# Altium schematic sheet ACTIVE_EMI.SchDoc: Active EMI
size A4; DrawnBy: Hely Zhang; Organization: Altium Limited; Address1: L3, 12a Rodborough Rd; Address2: Frenchs Forest; Address3: NSW; Address4: Australia 2086; DocumentNumber: 6; SheetNumber: 6; SheetTotal: 6; PageSetup: Record=PageOptions¦CenterHorizontal=True¦CenterVertical=True¦PrintScale=0.93¦XCorrection=1.00¦YCorrection=1.00¦PrintKind=0¦BorderSize=5000000¦LeftOffset=0¦BottomOffset=0¦Orientation=2¦PaperLength=1000¦PaperWidth=1000¦Scale=100¦PaperSource=15¦PrintQuality=600¦MediaType=1¦DitherType=10¦PaperKind=Letter¦PrintScaleMode=1
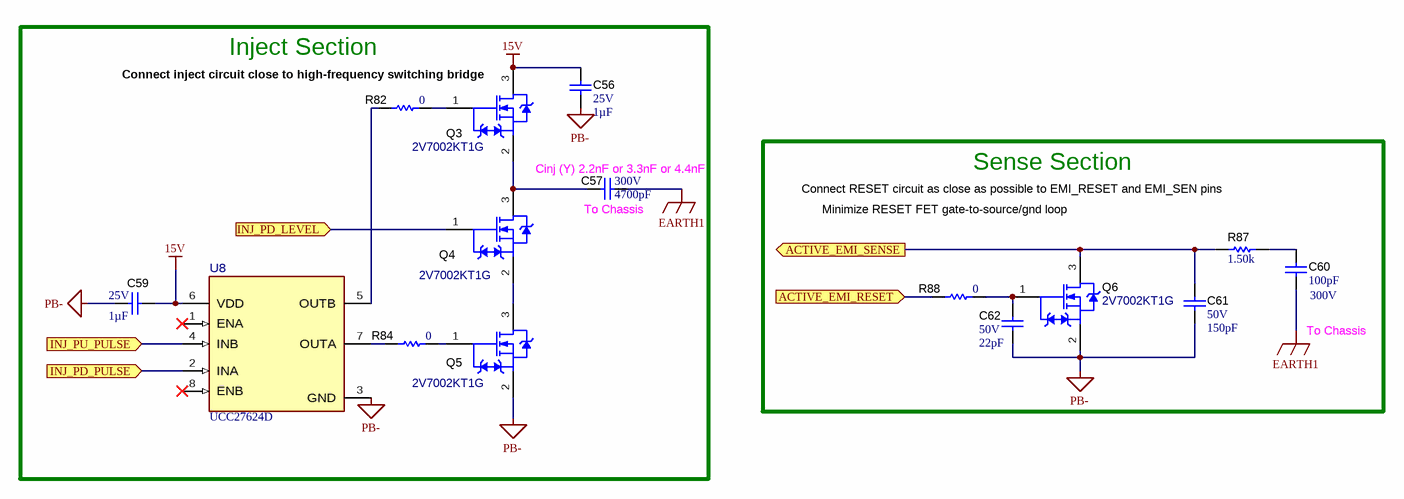
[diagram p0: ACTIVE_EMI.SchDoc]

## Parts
C56  VDC_V: 25V  Cap_F: 1µF  [0603]  (hidden comment: GRJ188R71E105KE11D)
C57  VDC_V: 300V  ValueDisplayed: 4700pF  [AY2_1300x500_Straight]  (hidden comment: AY2472M49Y5US63L7)
C59  VDC_V: 25V  Cap_F: 1µF  [0603]  (hidden comment: GRJ188R71E105KE11D)
C60  ValueDisplayed: 100pF  VAC_Y: 300V  [KY_700x500x1000]  (hidden comment: DE2B3KY101KN3AU02F)
C61  VDC_V: 50V  ValueDisplayed: 150pF  [0603]  (hidden comment: GRM1885C1H151JA01D)
C62  VDC_V: 50V  ValueDisplayed: 22pF  [0603]  (hidden comment: GRM1885C1H220JA01D)
Q3  2V7002KT1G  [SOT-23]
Q4  2V7002KT1G  [SOT-23]
Q5  2V7002KT1G  [SOT-23]
Q6  2V7002KT1G  [SOT-23]
R82  ValueDisplayed: 0  [0603]  (hidden comment: RC0603JR-070RL)
R84  ValueDisplayed: 0  [0603]  (hidden comment: RC0603JR-070RL)
R87  ValueDisplayed: 1.50k  [0603]  (hidden comment: RC0603FR-071K5L)
R88  ValueDisplayed: 0  [0603]  (hidden comment: RC0603JR-070RL)
U8  UCC27624D  [D0008A-MFG]

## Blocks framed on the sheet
Inject Section: C56 C57 C59 Q3-Q5 R82 R84 U8
Sense Section: C60-C62 Q6 R87 R88

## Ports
ACTIVE_EMI_RESET (in), ACTIVE_EMI_SENSE (out), INJ_PD_LEVEL (in), INJ_PD_PULSE (in), INJ_PU_PULSE (in)

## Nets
15V: C56.1 C59.1 Q3.3(D) U8.6(VDD)
EARTH1: C57.2 C60.1
PB-: C56.2 C59.2 C61.2 C62.2 Q5.2(S) Q6.2(S) U8.3(GND)
ACTIVE_EMI_RESET: R88.1 ; port ACTIVE_EMI_RESET
ACTIVE_EMI_SENSE: C61.1 Q6.3(D) R87.2 ; port ACTIVE_EMI_SENSE
INJ_PD_LEVEL: Q4.1(G) ; port INJ_PD_LEVEL
INJ_PD_PULSE: U8.2(INA) ; port INJ_PD_PULSE
INJ_PU_PULSE: U8.4(INB) ; port INJ_PU_PULSE
NetC57_1: C57.1 Q3.2(S) Q4.3(D)
NetC60_2: C60.2 R87.1
NetC62_1: C62.1 Q6.1(G) R88.2
NetQ3_1: Q3.1(G) R82.2
NetQ4_2: Q4.2(S) Q5.3(D)
NetQ5_1: Q5.1(G) R84.2
NetR82_1: R82.1 U8.5(OUTB)
NetR84_1: R84.1 U8.7(OUTA)

Not connected (* = marked no-connect by the designer): U8 1(ENA)* 8(ENB)*

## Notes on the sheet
- (near Q3) Connect inject circuit close to high-frequency switching bridge
- (near C57) Cinj (Y) 2.2nF or 3.3nF or 4.4nF
- Connect RESET circuit as close as possible to EMI_RESET and EMI_SEN pins
- (near C57) To Chassis
- Minimize RESET FET gate-to-source/gnd loop
- (near C60) To Chassis

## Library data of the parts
C56 C59 = CMP-0079720-2: CAP, CERM, 1 µF, 25 V,+/- 10%, X7R, 0603; Manufacturer: MuRata; AEC Category: Q200; TaMin_C: -55°C; AEC Qualified: N; SizeAreaWB_mm2: 4.68; SizeArea_mm2: 1.28; Value: 1uF; SizeZ_mm: 1; SizeX_mm: 1.6; U/M: EA; MFG_Status: TI_Obsolete; SizeY_mm: 0.8; TaMax_C: 125°C
C57 = CMP-0009589-2: CAP, CERM, 4700 pF, 300 V, +/- 20%, Y5U, AEC-Q200 Grade 1, D13xT5mm; Manufacturer: Vishay-Bccomponents; TaMin_C: -55°C; Polarized: N; SizeAreaWB_mm2: 105; Value1: Unknown; U/M: EA; Value: 4700pF; TaMax_C: 125°C; SizeZ_mm: 18; SizeX_mm: 13; SizeY_mm: 5; Cap_Case: 13x5mm; SizeArea_mm2: 65; AEC Qualified: Y; Cap_F: 4.7nF; AEC Grade: 1; AEC Category: Q200
C60 = CMP-0009606-4: CAP, CERM, 100 pF, X1 250 VAC/Y2 300 VAC, +/- 10%, B, TH; Manufacturer: MuRata; TaMin_C: -25°C; Polarized: N; SizeAreaWB_mm2: 66.5; Value1: Unknown; U/M: EA; Value: 100pF; TaMax_C: 85°C; SizeZ_mm: 10; SizeX_mm: 7.5; SizeY_mm: 5; Cap_Case: 7x5x10mm; SizeArea_mm2: 37.5; AEC Category: Q200; AC_Safety: X1Y2; VAC_X: 250V
C61 = CMP-0007185-4: CAP, CERM, 150 pF, 50 V, +/- 5%, C0G/NP0, 0603; Manufacturer: MuRata; TaMin_C: -55°C; Polarized: N; SizeAreaWB_mm2: 4.68; Value1: Unknown; U/M: EA; Value: 150pF; TaMax_C: 125°C; SizeZ_mm: 1; SizeX_mm: 1.6; SizeY_mm: 0.8; SizeArea_mm2: 1.28; AEC Category: Q200
C62 = CMP-0007196-4: CAP, CERM, 22 pF, 50 V, +/- 5%, C0G/NP0, 0603; Manufacturer: MuRata; TaMin_C: -55°C; Polarized: N; SizeAreaWB_mm2: 4.68; Value1: Unknown; U/M: EA; Value: 22pF; TaMax_C: 125°C; SizeZ_mm: 1; SizeX_mm: 1.6; SizeY_mm: 0.8; SizeArea_mm2: 1.28; AEC Category: Q200
Q3-Q6 = CMP-0000777-1: MOSFET, N-CH, 60 V, 0.32 A, AEC-Q101, SOT-23; Alternate Manufacturer: None; Manufacturer: ON Semiconductor; SizeZ_mm: 1.1; ChType: N; Value2: 0.7 nC; Value1: 2; VdsMax_V: 60V; SizeX_mm: 2.5; SizeY_mm: 3; Vgs_V: 20V; AEC Qualified: Y; Value: 60V; SizeArea_mm2: 7.5; AEC Category: Q101; IdsMax_A: 320mA; SizeAreaWB_mm2: 14; U/M: EA; QgTyp_nC: 0.7
R82 R84 R88 = CMP-0025885-5: RES, 0, 5%, 0.1 W, 0603; Manufacturer: Yageo; Power_W: 100mW; TempCo: 200 ppm/C; Value_Code: 0000; Value: 0; EIA_Code: E24; SizeX_mm: 1.6; SizeZ_mm: 1; Value2: 0.1W; SizeArea_mm2: 1.28; AEC Qualified: N; VDC_V: 75V; AEC Category: Q200; SizeY_mm: 0.8; SizeAreaWB_mm2: 4.68
R87 = CMP-0022883-5: RES, 1.50 k, 1%, 0.1 W, 0603; Manufacturer: Yageo; Power_W: 100mW; TempCo: 100 ppm/C; Value_Code: 1k50; Value: 1.50k; EIA_Code: E96; Res_ohm: 1.5k; SizeX_mm: 1.6; SizeY_mm: 0.8; SizeZ_mm: 1; Value2: 0.1W; SizeArea_mm2: 1.28; AEC Qualified: N; VDC_V: 75V; AEC Category: Q200; SizeAreaWB_mm2: 4.68
U8 = CMP-0091920-1: Dual Channel 30-V 5-A High-Speed Low-Side Gate Driver; Manufacturer: Texas Instruments; Max Supply Voltage: 26V; Propagation Delay: 17ns; Rise Time: 9ns; Standoff Height: 0.11mm; Min Supply Voltage: 4.5V; Nominal Supply Current: 175uA; Fall Time: 5ns; SizeZ_mm: 1.75mm; AEC Qualified: No; Number Of Outputs: 2; TJmax_C: +150°C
